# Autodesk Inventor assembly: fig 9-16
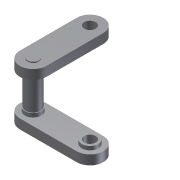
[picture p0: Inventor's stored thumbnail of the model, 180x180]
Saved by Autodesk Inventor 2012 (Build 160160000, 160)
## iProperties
Shininess: 64.0
Length Units: 11269
Angle Units: 11279
Time Units: 11290
Mass Units: 11283
Length Display Precision: 3
Angle Display Precision: 2
Created: 2002-01
Part Number: fig 9-16
Document SubType Name: Assembly
Designer: ***
Density: 0.0
Volumn: 0.0
Area: 0.0
PropertySet Name: Model Information
Control State: 0
Master: False
Checked Out: False
Author: ***
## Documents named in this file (3)
- C:\Users\CadCim\Documents\SAILESH\inventor-2011-fact-prt\c09_inv_2011-prt\c09_inv_2012_prt\fig 9-16.iam
- C:\Users\CadCim\Documents\SAILESH\inventor-2011-fact-prt\c09_inv_2011-prt\c09_inv_2012_prt\Part5.ipt
- C:\Users\CadCim\Documents\SAILESH\inventor-2011-fact-prt\c09_inv_2011-prt\c09_inv_2012_prt\Part6.ipt
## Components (3 placed, 2 different names)
1. Part5:1 — Insert:1, Angle:1
2. Part6:1 — Insert:1, Insert:2
3. Part5:2 — Insert:2, Angle:1
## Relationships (3: Insert 2, Angle 1)
- Insert:1: Part5:1 ↔ Part6:1
- Insert:2: Part6:1 ↔ Part5:2
- Angle:1: Part5:1 ↔ Part5:2
